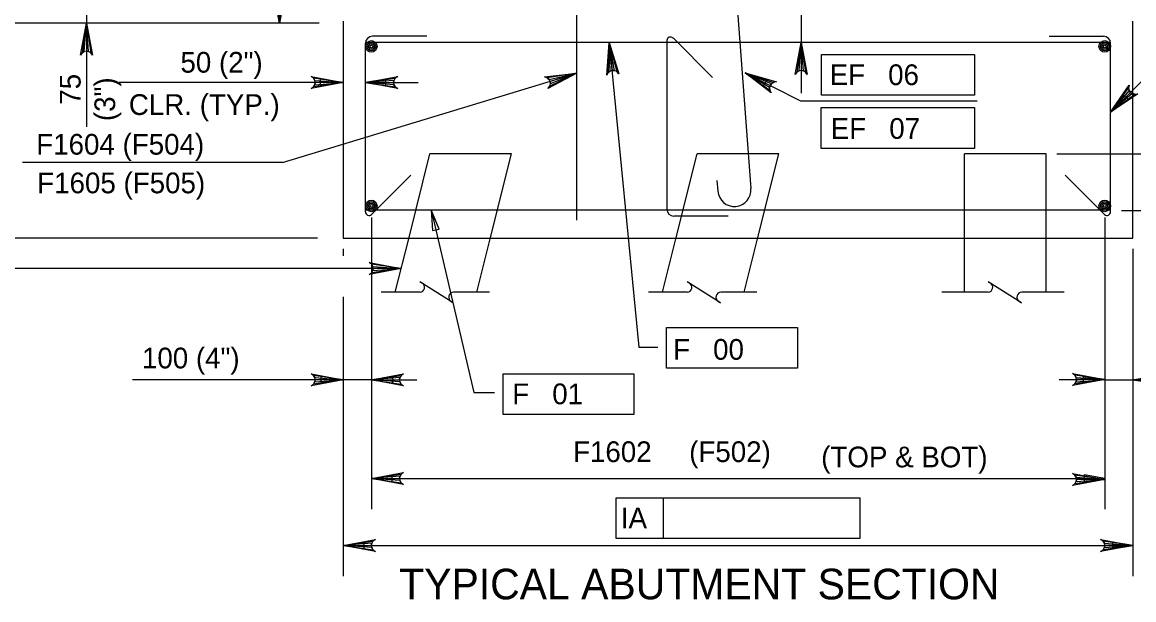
# Model space of a CAD drawing. Extents: x 638340 to 640241, y 295465 to 298435.
# Drawn here: x 639020.2 to 639181.1, y 296953.5 to 297037.2 of the extents above; entities that cross this region are included whole.
import ezdxf

# ---------------------------------------------------------------- set-up
doc = ezdxf.new("R2010")
doc.units = 0
for name, color, linetype in [('3', 7, 'Continuous'), ('4', 7, 'Continuous'), ('5', 7, 'Continuous'), ('7', 7, 'Continuous'), ('8', 7, 'Continuous'), ('9', 7, 'Continuous')]:
    doc.layers.add(name, color=color, linetype=linetype)

msp = doc.modelspace()

# ---------------------------------------------------------------- linework, layer by layer
at = {"layer": '3'}
for p, q in [((639057.44, 297037.02), (639057.44, 297074.72)), ((639029.48, 297039.86), (639029.48, 297031.11)), ((639063.19, 297037.02), (639007.56, 297037.02)), ((639037.62, 297037.02), (639025.05, 297037.02)), ((639029.48, 297037.02), (639029.48, 297022.03)), ((639105.13, 297034.22), (639109.41, 296990.09)), ((639177.72, 297024.12), (639187.29, 297033.66)), ((639135.87, 297032.49), (639158.02, 297032.49)), ((639135.87, 297026.58), (639135.87, 297032.49)), ((639158.02, 297032.49), (639158.02, 297026.58)), ((639124.82, 297029.81), (639132.85, 297025.76)), ((639066.65, 297028.42), (639034.22, 297028.42)), ((639069.87, 297028.42), (639077.51, 297028.42)), ((639158.02, 297026.58), (639135.87, 297026.58)), ((639132.85, 297025.76), (639158.39, 297025.76)), ((639135.83, 297024.8), (639158.02, 297024.8)), ((639135.83, 297018.89), (639135.83, 297024.8)), ((639158.02, 297024.8), (639158.02, 297018.89)), ((639158.02, 297018.89), (639135.83, 297018.89)), ((639057.85, 297016.84), (639020.21, 297016.84)), ((639169.92, 297018.09), (639225.99, 297018.09)), ((639070.72, 297008.89), (639070.72, 297003.87)), ((639070.72, 297008.76), (639070.72, 296995.34)), ((639079.38, 297009.98), (639085.57, 296983.56)), ((639176.86, 297008.89), (639176.86, 296966.68)), ((639179.28, 297009.89), (639212.28, 297009.89)), ((639062.93, 297005.88), (638990.56, 297005.88)), ((639066.65, 297004.34), (639066.65, 297003.35)), ((639180.93, 297004.34), (639180.93, 296956.97)), ((639075.05, 297001.5), (639001.3, 297001.5)), ((639066.65, 296997.39), (639066.65, 296956.97)), ((639070.72, 296997.04), (639070.72, 296966.68)), ((639113.43, 296992.96), (639132.38, 296992.96)), ((639113.43, 296987.06), (639113.43, 296992.96)), ((639132.38, 296992.96), (639132.38, 296987.06)), ((639109.41, 296990.09), (639112.17, 296990.09)), ((639089.79, 296986.27), (639108.73, 296986.27)), ((639089.79, 296980.37), (639089.79, 296986.27)), ((639108.73, 296986.27), (639108.73, 296980.37)), ((639132.38, 296987.06), (639113.43, 296987.06)), ((639070.72, 296985.4), (639036.16, 296985.4)), ((639070.72, 296985.4), (639077.31, 296985.4)), ((639173.78, 296985.4), (639170.27, 296985.4)), ((639176.86, 296985.4), (639215.58, 296985.4)), ((639085.57, 296983.56), (639088.53, 296983.56)), ((639180.93, 296984.03), (639180.93, 296976.09)), ((639108.73, 296980.37), (639089.79, 296980.37)), ((639070.72, 296971.11), (639174.59, 296971.11)), ((639106.14, 296968.32), (639112.98, 296968.32)), ((639106.14, 296962.41), (639106.14, 296968.32)), ((639112.98, 296962.41), (639112.98, 296968.32)), ((639112.98, 296968.32), (639141.44, 296968.32)), ((639141.44, 296968.32), (639141.44, 296962.41)), ((639141.44, 296962.41), (639106.14, 296962.41)), ((639066.65, 296961.4), (639180.93, 296961.4))]:
    msp.add_line(p, q, dxfattribs=at)
for points in [[(639057.44, 297037.02), (639056.56, 297041.68), (639056.81, 297041.32), (639057.12, 297041.14), (639057.44, 297041.08), (639057.75, 297041.14), (639058.06, 297041.32), (639058.31, 297041.68), (639057.44, 297037.02), (639058.06, 297041.32), (639057.75, 297041.14), (639057.44, 297037.02), (639057.44, 297041.08), (639057.12, 297041.14), (639057.44, 297037.02), (639056.81, 297041.32)], [(639105.13, 297034.22), (639106.53, 297029.68), (639106.24, 297030.01), (639105.9, 297030.16), (639105.59, 297030.18), (639105.28, 297030.09), (639104.99, 297029.87), (639104.79, 297029.49), (639105.13, 297034.22), (639104.99, 297029.87), (639105.28, 297030.09), (639105.13, 297034.22), (639105.59, 297030.18), (639105.9, 297030.16), (639105.13, 297034.22), (639106.24, 297030.01)], [(639132.94, 297034.22), (639133.81, 297029.56), (639133.56, 297029.91), (639133.25, 297030.1), (639132.94, 297030.15), (639132.62, 297030.1), (639132.31, 297029.91), (639132.06, 297029.56), (639132.94, 297034.22), (639132.31, 297029.91), (639132.62, 297030.1), (639132.94, 297034.22), (639132.94, 297030.15), (639133.25, 297030.1), (639132.94, 297034.22), (639133.56, 297029.91)], [(639124.82, 297029.81), (639129.38, 297028.5), (639128.94, 297028.43), (639128.64, 297028.24), (639128.45, 297027.98), (639128.36, 297027.68), (639128.38, 297027.32), (639128.59, 297026.93), (639124.82, 297029.81), (639128.38, 297027.32), (639128.36, 297027.68), (639124.82, 297029.81), (639128.45, 297027.98), (639128.64, 297028.24), (639124.82, 297029.81), (639128.94, 297028.43)], [(639066.65, 297028.42), (639061.99, 297027.54), (639062.35, 297027.79), (639062.53, 297028.1), (639062.59, 297028.42), (639062.53, 297028.73), (639062.35, 297029.04), (639061.99, 297029.29), (639066.65, 297028.42), (639062.35, 297029.04), (639062.53, 297028.73), (639066.65, 297028.42), (639062.59, 297028.42), (639062.53, 297028.1), (639066.65, 297028.42), (639062.35, 297027.79)], [(639069.87, 297028.42), (639074.53, 297029.29), (639074.17, 297029.04), (639073.98, 297028.73), (639073.93, 297028.42), (639073.98, 297028.1), (639074.17, 297027.79), (639074.53, 297027.54), (639069.87, 297028.42), (639074.17, 297027.79), (639073.98, 297028.1), (639069.87, 297028.42), (639073.93, 297028.42), (639073.98, 297028.73), (639069.87, 297028.42), (639074.17, 297029.04)], [(639177.72, 297024.12), (639180.4, 297028.03), (639180.32, 297027.6), (639180.41, 297027.25), (639180.59, 297026.99), (639180.85, 297026.81), (639181.2, 297026.72), (639181.64, 297026.79), (639177.72, 297024.12), (639181.2, 297026.72), (639180.85, 297026.81), (639177.72, 297024.12), (639180.59, 297026.99), (639180.41, 297027.25), (639177.72, 297024.12), (639180.32, 297027.6)], [(639075.05, 297001.5), (639070.39, 297000.63), (639070.75, 297000.88), (639070.94, 297001.19), (639070.99, 297001.5), (639070.94, 297001.81), (639070.75, 297002.13), (639070.39, 297002.37), (639075.05, 297001.5), (639070.75, 297002.13), (639070.94, 297001.81), (639075.05, 297001.5), (639070.99, 297001.5), (639070.94, 297001.19), (639075.05, 297001.5), (639070.75, 297000.88)], [(639066.65, 296985.4), (639061.99, 296984.53), (639062.35, 296984.78), (639062.53, 296985.09), (639062.59, 296985.4), (639062.53, 296985.71), (639062.35, 296986.03), (639061.99, 296986.27), (639066.65, 296985.4), (639062.35, 296986.03), (639062.53, 296985.71), (639066.65, 296985.4), (639062.59, 296985.4), (639062.53, 296985.09), (639066.65, 296985.4), (639062.35, 296984.78)], [(639070.72, 296985.4), (639075.38, 296986.27), (639075.02, 296986.03), (639074.83, 296985.71), (639074.78, 296985.4), (639074.83, 296985.09), (639075.02, 296984.78), (639075.38, 296984.53), (639070.72, 296985.4), (639075.02, 296984.78), (639074.83, 296985.09), (639070.72, 296985.4), (639074.78, 296985.4), (639074.83, 296985.71), (639070.72, 296985.4), (639075.02, 296986.03)], [(639176.86, 296985.42), (639172.2, 296984.55), (639172.56, 296984.8), (639172.75, 296985.11), (639172.8, 296985.42), (639172.75, 296985.74), (639172.56, 296986.05), (639172.2, 296986.3), (639176.86, 296985.42), (639172.56, 296986.05), (639172.75, 296985.74), (639176.86, 296985.42), (639172.8, 296985.42), (639172.75, 296985.11), (639176.86, 296985.42), (639172.56, 296984.8)], [(639180.93, 296985.4), (639185.59, 296986.27), (639185.23, 296986.03), (639185.05, 296985.71), (639184.99, 296985.4), (639185.05, 296985.09), (639185.23, 296984.78), (639185.59, 296984.53), (639180.93, 296985.4), (639185.23, 296984.78), (639185.05, 296985.09), (639180.93, 296985.4), (639184.99, 296985.4), (639185.05, 296985.71), (639180.93, 296985.4), (639185.23, 296986.03)], [(639070.72, 296971.11), (639075.38, 296971.99), (639075.02, 296971.74), (639074.83, 296971.43), (639074.78, 296971.11), (639074.83, 296970.8), (639075.02, 296970.49), (639075.38, 296970.24), (639070.72, 296971.11), (639075.02, 296970.49), (639074.83, 296970.8), (639070.72, 296971.11), (639074.78, 296971.11), (639074.83, 296971.43), (639070.72, 296971.11), (639075.02, 296971.74)], [(639176.86, 296970.97), (639172.2, 296970.1), (639172.56, 296970.35), (639172.75, 296970.66), (639172.8, 296970.97), (639172.75, 296971.28), (639172.56, 296971.6), (639172.2, 296971.84), (639176.86, 296970.97), (639172.56, 296971.6), (639172.75, 296971.28), (639176.86, 296970.97), (639172.8, 296970.97), (639172.75, 296970.66), (639176.86, 296970.97), (639172.56, 296970.35)], [(639066.65, 296961.4), (639071.31, 296962.28), (639070.95, 296962.03), (639070.77, 296961.72), (639070.71, 296961.4), (639070.77, 296961.09), (639070.95, 296960.78), (639071.31, 296960.53), (639066.65, 296961.4), (639070.95, 296960.78), (639070.77, 296961.09), (639066.65, 296961.4), (639070.71, 296961.4), (639070.77, 296961.72), (639066.65, 296961.4), (639070.95, 296962.03)], [(639180.93, 296961.4), (639176.27, 296960.53), (639176.63, 296960.78), (639176.81, 296961.09), (639176.87, 296961.4), (639176.81, 296961.72), (639176.63, 296962.03), (639176.27, 296962.28), (639180.93, 296961.4), (639176.63, 296962.03), (639176.81, 296961.72), (639180.93, 296961.4), (639176.87, 296961.4), (639176.81, 296961.09), (639180.93, 296961.4), (639176.63, 296960.78)]]:
    msp.add_lwpolyline(points, dxfattribs=at)
for points in [[(639104.97, 297031.23), (639105.95, 297031.34), (639105.13, 297034.22)], [(639127.54, 297027.89), (639127.98, 297028.77), (639125.13, 297029.66)], [(639063.29, 297028.91), (639063.29, 297027.92), (639066.24, 297028.42)], [(639072.82, 297027.92), (639072.82, 297028.91), (639069.87, 297028.42)], [(639180.25, 297025.96), (639179.56, 297026.65), (639177.82, 297024.22)], [(639079.56, 297006.99), (639080.52, 297007.21), (639079.38, 297009.98)], [(639063.42, 296985.89), (639063.42, 296984.91), (639066.38, 296985.4)], [(639073.81, 296984.91), (639073.81, 296985.89), (639070.85, 296985.4)], [(639173.78, 296984.91), (639173.78, 296985.89), (639176.73, 296985.4)], [(639073.67, 296971.61), (639073.67, 296970.62), (639070.72, 296971.11)], [(639173.91, 296971.61), (639173.91, 296970.62), (639176.86, 296971.11)], [(639069.61, 296961.89), (639069.61, 296960.91), (639066.65, 296961.4)], [(639177.98, 296961.89), (639177.98, 296960.91), (639180.93, 296961.4)]]:
    msp.add_lwpolyline(points, close=True, dxfattribs=at)
at = {"layer": '4'}
for p, q in [((639132.95, 297043.19), (639132.95, 297026.88)), ((639057.85, 297016.84), (639100.47, 297029.76))]:
    msp.add_line(p, q, dxfattribs=at)
for points in [[(639029.48, 297037.02), (639030.35, 297032.36), (639030.11, 297032.72), (639029.79, 297032.9), (639029.48, 297032.96), (639029.17, 297032.9), (639028.86, 297032.72), (639028.61, 297032.36), (639029.48, 297037.02), (639028.86, 297032.72), (639029.17, 297032.9), (639029.48, 297037.02), (639029.48, 297032.96), (639029.79, 297032.9), (639029.48, 297037.02), (639030.11, 297032.72)], [(639100.48, 297029.76), (639096.27, 297027.57), (639096.54, 297027.91), (639096.63, 297028.27), (639096.59, 297028.58), (639096.45, 297028.86), (639096.18, 297029.11), (639095.76, 297029.25), (639100.48, 297029.76), (639096.18, 297029.11), (639096.45, 297028.86), (639100.48, 297029.76), (639096.59, 297028.58), (639096.63, 297028.27), (639100.48, 297029.76), (639096.54, 297027.91)], [(639100.48, 297029.76), (639096.27, 297027.57), (639096.54, 297027.91), (639096.63, 297028.27), (639096.59, 297028.58), (639096.45, 297028.86), (639096.18, 297029.11), (639095.76, 297029.25), (639100.48, 297029.76), (639096.18, 297029.11), (639096.45, 297028.86), (639100.48, 297029.76), (639096.59, 297028.58), (639096.63, 297028.27), (639100.48, 297029.76), (639096.54, 297027.91)]]:
    msp.add_lwpolyline(points, dxfattribs=at)
at = {"layer": '5'}
for p, q in [((639120.49, 297081.78), (639125.65, 297013.08)), ((639100.48, 297008.5), (639100.48, 297057.67)), ((639078.75, 297035.11), (639070.89, 297035.11)), ((639113.5, 297034.5), (639113.5, 297010.11)), ((639120.08, 297029.16), (639114.38, 297034.87)), ((639168.84, 297035.11), (639176.69, 297035.11)), ((639177.71, 297034.22), (639069.87, 297034.22)), ((639069.87, 297009.69), (639069.87, 297034.09)), ((639177.72, 297009.69), (639177.72, 297034.09)), ((639076.45, 297015.03), (639070.74, 297009.33)), ((639171.14, 297015.03), (639176.84, 297009.33)), ((639120.74, 297014.22), (639120.87, 297012.68)), ((639069.87, 297009.98), (639177.72, 297009.98)), ((639122.38, 297009.08), (639114.53, 297009.08))]:
    msp.add_line(p, q, dxfattribs=at)
for centre, radius in [((639070.72, 297033.65), 0.833), ((639176.86, 297033.65), 0.833), ((639070.72, 297033.65), 0.625), ((639070.72, 297033.65), 0.417), ((639070.72, 297033.65), 0.208), ((639176.86, 297033.65), 0.625), ((639176.86, 297033.65), 0.417), ((639176.86, 297033.65), 0.208), ((639070.72, 297010.56), 0.833), ((639070.72, 297010.56), 0.625), ((639070.72, 297010.56), 0.417), ((639070.72, 297010.56), 0.208), ((639176.86, 297010.56), 0.833), ((639176.86, 297010.56), 0.625), ((639176.86, 297010.56), 0.417), ((639176.86, 297010.56), 0.208)]:
    msp.add_circle(centre, radius, dxfattribs=at)
for centre, radius, start, end in [((639070.89, 297034.09), 1.03, 90, 180), ((639114.01, 297034.5), 0.512, 45, 180), ((639176.69, 297034.09), 1.03, 0, 90), ((639123.26, 297012.88), 2.4, 184.7636, 4.7636), ((639070.38, 297009.69), 0.512, 180, 315), ((639114.52, 297010.11), 1.03, 180, 270), ((639177.2, 297009.69), 0.512, 225, 0)]:
    msp.add_arc(centre, radius, start, end, dxfattribs=at)
at = {"layer": '7'}
msp.add_line((639066.26, 297037.02), (639066.26, 297037.02), dxfattribs=at)
at = {"layer": '8'}
for p, q in [((639076.13, 297005.79), (639079.2, 297018.09)), ((639091.01, 297018.09), (639079.2, 297018.09)), ((639087.94, 297005.79), (639091.01, 297018.09)), ((639114.81, 297005.79), (639117.88, 297018.09)), ((639129.7, 297018.09), (639117.88, 297018.09)), ((639126.62, 297005.79), (639129.7, 297018.09)), ((639168.38, 297018.09), (639156.57, 297018.09)), ((639156.57, 297005.88), (639156.57, 297018.09)), ((639168.38, 297005.79), (639168.38, 297018.09)), ((639074.19, 296998.06), (639076.13, 297005.79)), ((639086, 296998.06), (639087.94, 297005.79)), ((639112.88, 296998.06), (639114.81, 297005.79)), ((639124.69, 296998.06), (639126.62, 297005.79)), ((639156.57, 296998.06), (639156.57, 297005.88)), ((639168.38, 296998.06), (639168.38, 297005.79)), ((639077.77, 296998.06), (639072.16, 296998.06)), ((639087.81, 296998.06), (639082.62, 296998.06)), ((639116.45, 296998.06), (639110.85, 296998.06)), ((639126.5, 296998.06), (639121.31, 296998.06)), ((639160.01, 296998.06), (639153.27, 296998.06)), ((639171.01, 296998.06), (639164.86, 296998.06))]:
    msp.add_line(p, q, dxfattribs=at)
for points in [[(639082.27, 296996.74), (639082.57, 296996.55), (639077.76, 296999.57), (639078.08, 296999.37)], [(639120.95, 296996.74), (639121.25, 296996.55), (639116.44, 296999.57), (639116.76, 296999.37)], [(639164.51, 296996.74), (639164.81, 296996.55), (639160, 296999.57), (639160.32, 296999.37)]]:
    msp.add_lwpolyline(points, dxfattribs=at)
for centre, start, end in [((639077.7, 296998.77), 275.3286, 57.8672), ((639116.39, 296998.77), 275.3286, 57.8672), ((639159.94, 296998.77), 275.3286, 57.8672), ((639082.62, 296997.35), 90, 240), ((639121.31, 296997.35), 90, 240), ((639164.86, 296997.35), 90, 240)]:
    msp.add_arc(centre, 0.71, start, end, dxfattribs=at)
at = {"layer": '9'}
for p, q in [((639066.65, 297037.29), (639066.65, 297005.88)), ((639180.93, 297005.88), (639180.93, 297037.29)), ((639066.65, 297005.88), (639180.93, 297005.88))]:
    msp.add_line(p, q, dxfattribs=at)

# ---------------------------------------------------------------- texts
at = {"layer": '3'}
for s, height, p in [('50 (2")', 3, (639043.09, 297029.85)), ('EF   06', 3, (639137.05, 297028.05)), ('CLR. (TYP.)', 3.0001, (639035.62, 297023.73)), ('EF   07', 3, (639137.21, 297020.27)), ('F1604 (F504)', 3.0001, (639022.22, 297017.98)), ('F1605 (F505)', 3.0001, (639022.36, 297012.39)), ('F   00', 3, (639114.39, 296988.29)), ('100 (4")', 3, (639037.52, 296987.04)), ('F   01', 3, (639091.11, 296981.85)), ('F1602', 3, (639099.91, 296973.48)), ('(F502)', 3, (639116.72, 296973.48)), ('(TOP & BOT)', 3.0001, (639135.83, 296972.72)), ('IA', 3, (639106.83, 296963.89)), ('TYPICAL ABUTMENT SECTION', 4.4294, (639074.75, 296953.61))]:
    msp.add_text(s, height=height, dxfattribs=at).set_placement(p)
for s, p in [('75', (639028.64, 297025.21)), ('(3")', (639033.64, 297022.84))]:
    msp.add_text(s, height=3, rotation=90, dxfattribs=at).set_placement(p)

doc.saveas('drawing.dxf')
